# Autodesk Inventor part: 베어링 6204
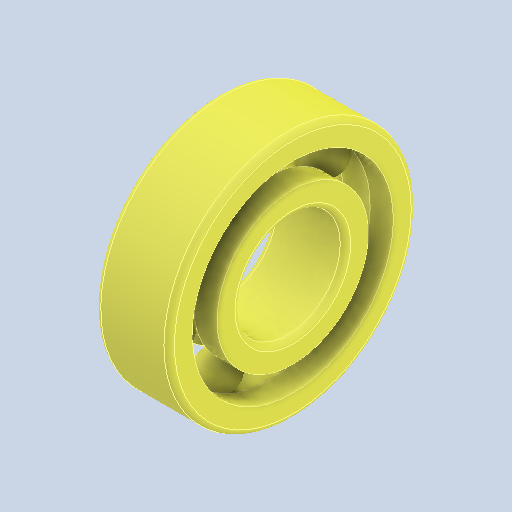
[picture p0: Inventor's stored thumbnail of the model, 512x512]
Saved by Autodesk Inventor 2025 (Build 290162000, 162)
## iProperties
Created: 2024-08
Part Number: 베어링 6204
Material: 스테인리스강
Description: 깊은 그루브 볼 베어링
Document SubType Name: Modeling
Designer: rese9
Density: 8.08 g/cm^3
Appearance: 기본값
Author: jhkim
Sending System: Autodesk Inventor 2025
Preprocessor: ST-DEVELOPER v20
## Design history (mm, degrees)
feature "Solid1"
feature "Solid1:1"
feature "Solid1:2"
feature "Solid1:3"
feature "Solid1:4"
feature "Solid1:5"
feature "Solid1:6"
feature "Solid1:7"
feature "Solid1:8"
node "솔리드1"
node "솔리드2"
node "솔리드3"
node "솔리드4"
node "솔리드5"
node "솔리드6"
node "솔리드7"
node "솔리드8"
node "솔리드9"
